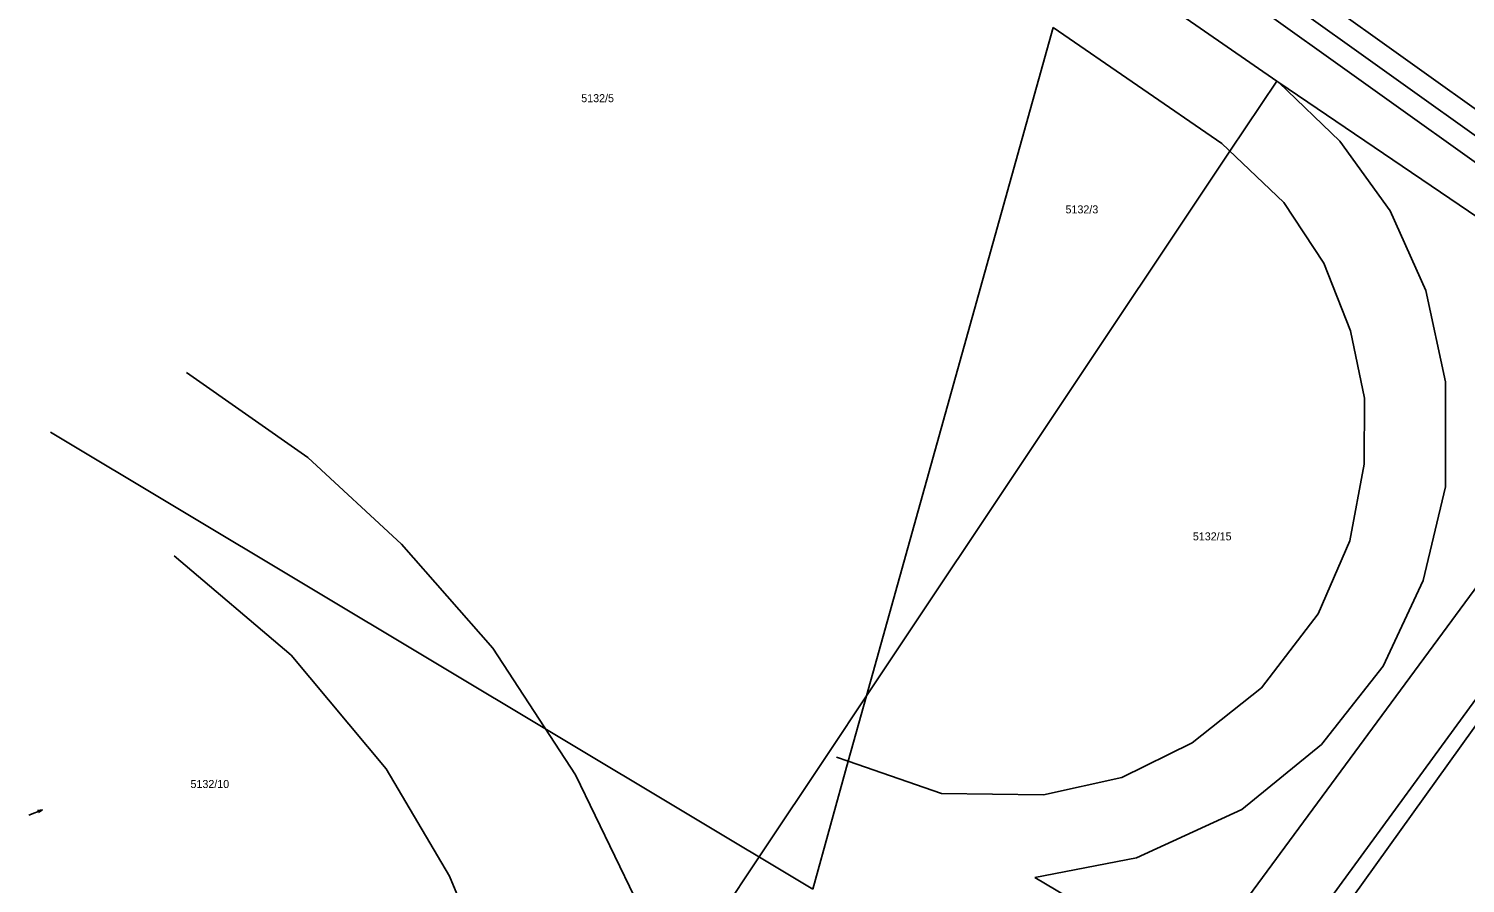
# Model space of a CAD drawing. Extents: x -400488 to -400124, y -1251493 to -1251223.
# Drawn here: x -400487.9 to -400401.8, y -1251405.1 to -1251353.8 of the extents above; entities that cross this region are included whole.
import ezdxf

# ---------------------------------------------------------------- set-up
doc = ezdxf.new("R2010")
doc.units = 0
doc.layers.add('Level 63', color=7, linetype='Continuous')

msp = doc.modelspace()

# ---------------------------------------------------------------- linework, layer by layer
at = {"layer": 'Level 63'}
for p, q in [((-400435.27, -1251334.27), (-400389.79, -1251366.78)), ((-400436.03, -1251335.33), (-400389.43, -1251368.65)), ((-400391.27, -1251368.93), (-400436.79, -1251336.39)), ((-400413.07, -1251356.97), (-400425.06, -1251348.67)), ((-400425.06, -1251348.67), (-400413.07, -1251356.97)), ((-400426.48, -1251353.77), (-400437.67, -1251393.84)), ((-400437.67, -1251393.84), (-400426.48, -1251353.77)), ((-400426.48, -1251353.77), (-400416.37, -1251360.72)), ((-400426.48, -1251353.77), (-400416.37, -1251360.72)), ((-400415.88, -1251361.18), (-400413.07, -1251356.97)), ((-400413.07, -1251356.97), (-400415.88, -1251361.18)), ((-400412.94, -1251357.06), (-400413.07, -1251356.97)), ((-400413.07, -1251356.97), (-400412.94, -1251357.06)), ((-400409.29, -1251360.58), (-400412.94, -1251357.06)), ((-400392.66, -1251370.85), (-400412.94, -1251357.06)), ((-400409.29, -1251360.58), (-400412.94, -1251357.06)), ((-400412.94, -1251357.06), (-400392.66, -1251370.85)), ((-400416.37, -1251360.72), (-400412.64, -1251364.25)), ((-400416.37, -1251360.72), (-400412.64, -1251364.25)), ((-400406.28, -1251364.76), (-400409.29, -1251360.58)), ((-400406.28, -1251364.76), (-400409.29, -1251360.58)), ((-400437.67, -1251393.84), (-400415.88, -1251361.18)), ((-400415.88, -1251361.18), (-400437.67, -1251393.84)), ((-400412.64, -1251364.25), (-400410.26, -1251367.89)), ((-400412.64, -1251364.25), (-400410.26, -1251367.89)), ((-400404.14, -1251369.54), (-400406.28, -1251364.76)), ((-400404.14, -1251369.54), (-400406.28, -1251364.76)), ((-400410.26, -1251367.89), (-400408.66, -1251371.96)), ((-400410.26, -1251367.89), (-400408.66, -1251371.96)), ((-400402.95, -1251375.02), (-400404.14, -1251369.54)), ((-400402.95, -1251375.02), (-400404.14, -1251369.54)), ((-400408.66, -1251371.96), (-400407.82, -1251376)), ((-400408.66, -1251371.96), (-400407.82, -1251376)), ((-400478.44, -1251374.46), (-400471.18, -1251379.55)), ((-400478.44, -1251374.46), (-400471.18, -1251379.55)), ((-400402.96, -1251381.3), (-400402.95, -1251375.02)), ((-400402.96, -1251381.3), (-400402.95, -1251375.02)), ((-400407.82, -1251376), (-400407.84, -1251379.95)), ((-400407.82, -1251376), (-400407.84, -1251379.95)), ((-400486.61, -1251378.03), (-400440.9, -1251405.43)), ((-400471.18, -1251379.55), (-400465.55, -1251384.75)), ((-400471.18, -1251379.55), (-400465.55, -1251384.75)), ((-400407.84, -1251379.95), (-400408.7, -1251384.55)), ((-400407.84, -1251379.95), (-400408.7, -1251384.55)), ((-400404.3, -1251386.92), (-400402.96, -1251381.3)), ((-400404.3, -1251386.92), (-400402.96, -1251381.3)), ((-400465.55, -1251384.75), (-400460.09, -1251390.99)), ((-400465.55, -1251384.75), (-400460.09, -1251390.99)), ((-400432.67, -1251430.17), (-400399.19, -1251384.72)), ((-400399.19, -1251384.72), (-400432.67, -1251430.17)), ((-400408.7, -1251384.55), (-400410.59, -1251388.93)), ((-400408.7, -1251384.55), (-400410.59, -1251388.93)), ((-400472.18, -1251391.4), (-400479.18, -1251385.45)), ((-400472.18, -1251391.4), (-400479.18, -1251385.45)), ((-400395.83, -1251386.77), (-400431.43, -1251435.5)), ((-400431.43, -1251435.5), (-400395.83, -1251386.77)), ((-400406.7, -1251392.07), (-400404.3, -1251386.92)), ((-400406.7, -1251392.07), (-400404.3, -1251386.92)), ((-400410.59, -1251388.93), (-400413.99, -1251393.36)), ((-400410.59, -1251388.93), (-400413.99, -1251393.36)), ((-400460.09, -1251390.99), (-400455.12, -1251398.59)), ((-400460.09, -1251390.99), (-400455.12, -1251398.59)), ((-400466.47, -1251398.23), (-400472.18, -1251391.4)), ((-400466.47, -1251398.23), (-400472.18, -1251391.4)), ((-400410.39, -1251396.77), (-400406.7, -1251392.07)), ((-400410.39, -1251396.77), (-400406.7, -1251392.07)), ((-400413.99, -1251393.36), (-400418.14, -1251396.66)), ((-400413.99, -1251393.36), (-400418.14, -1251396.66)), ((-400413.25, -1251412.5), (-400399.26, -1251392.99)), ((-400399.26, -1251392.99), (-400413.25, -1251412.5)), ((-400437.67, -1251393.84), (-400439.94, -1251397.25)), ((-400439.94, -1251397.25), (-400437.67, -1251393.84)), ((-400437.67, -1251393.84), (-400438.77, -1251397.77)), ((-400438.77, -1251397.77), (-400437.67, -1251393.84)), ((-400418.14, -1251396.66), (-400422.37, -1251398.75)), ((-400418.14, -1251396.66), (-400422.37, -1251398.75)), ((-400415.16, -1251400.67), (-400410.39, -1251396.77)), ((-400415.16, -1251400.67), (-400410.39, -1251396.77)), ((-400439.94, -1251397.25), (-400444.11, -1251403.5)), ((-400444.11, -1251403.5), (-400439.94, -1251397.25)), ((-400438.77, -1251397.77), (-400440.9, -1251405.43)), ((-400440.9, -1251405.43), (-400438.77, -1251397.77)), ((-400439.48, -1251397.53), (-400438.77, -1251397.77)), ((-400433.17, -1251399.7), (-400438.77, -1251397.77)), ((-400433.17, -1251399.7), (-400438.77, -1251397.77)), ((-400462.68, -1251404.65), (-400466.47, -1251398.23)), ((-400462.68, -1251404.65), (-400466.47, -1251398.23)), ((-400455.12, -1251398.59), (-400451.59, -1251405.9)), ((-400455.12, -1251398.59), (-400451.59, -1251405.9)), ((-400422.37, -1251398.75), (-400427.06, -1251399.79)), ((-400422.37, -1251398.75), (-400427.06, -1251399.79)), ((-400427.06, -1251399.79), (-400433.17, -1251399.7)), ((-400427.06, -1251399.79), (-400433.17, -1251399.7)), ((-400487.91, -1251401.01), (-400487.076, -1251400.672)), ((-400487.076, -1251400.672), (-400487.376, -1251400.729)), ((-400487.331, -1251400.84), (-400487.076, -1251400.672)), ((-400421.48, -1251403.56), (-400415.16, -1251400.67)), ((-400421.48, -1251403.56), (-400415.16, -1251400.67)), ((-400444.11, -1251403.5), (-400449.63, -1251411.78)), ((-400449.63, -1251411.78), (-400444.11, -1251403.5)), ((-400427.58, -1251404.74), (-400421.48, -1251403.56)), ((-400427.58, -1251404.74), (-400421.48, -1251403.56)), ((-400458.62, -1251414.42), (-400462.68, -1251404.65)), ((-400458.62, -1251414.42), (-400462.68, -1251404.65)), ((-400418.57, -1251410.06), (-400427.58, -1251404.74)), ((-400418.57, -1251410.06), (-400427.58, -1251404.74))]:
    msp.add_line(p, q, dxfattribs=at)

# ---------------------------------------------------------------- texts
for s, p in [('5132/5', (-400454.78, -1251358.24)), ('5132/3', (-400425.741, -1251364.91)), ('5132/15', (-400418.106, -1251384.52)), ('5132/10', (-400478.21, -1251399.37))]:
    msp.add_text(s, height=0.48, dxfattribs=at).set_placement(p)

doc.saveas('drawing.dxf')
